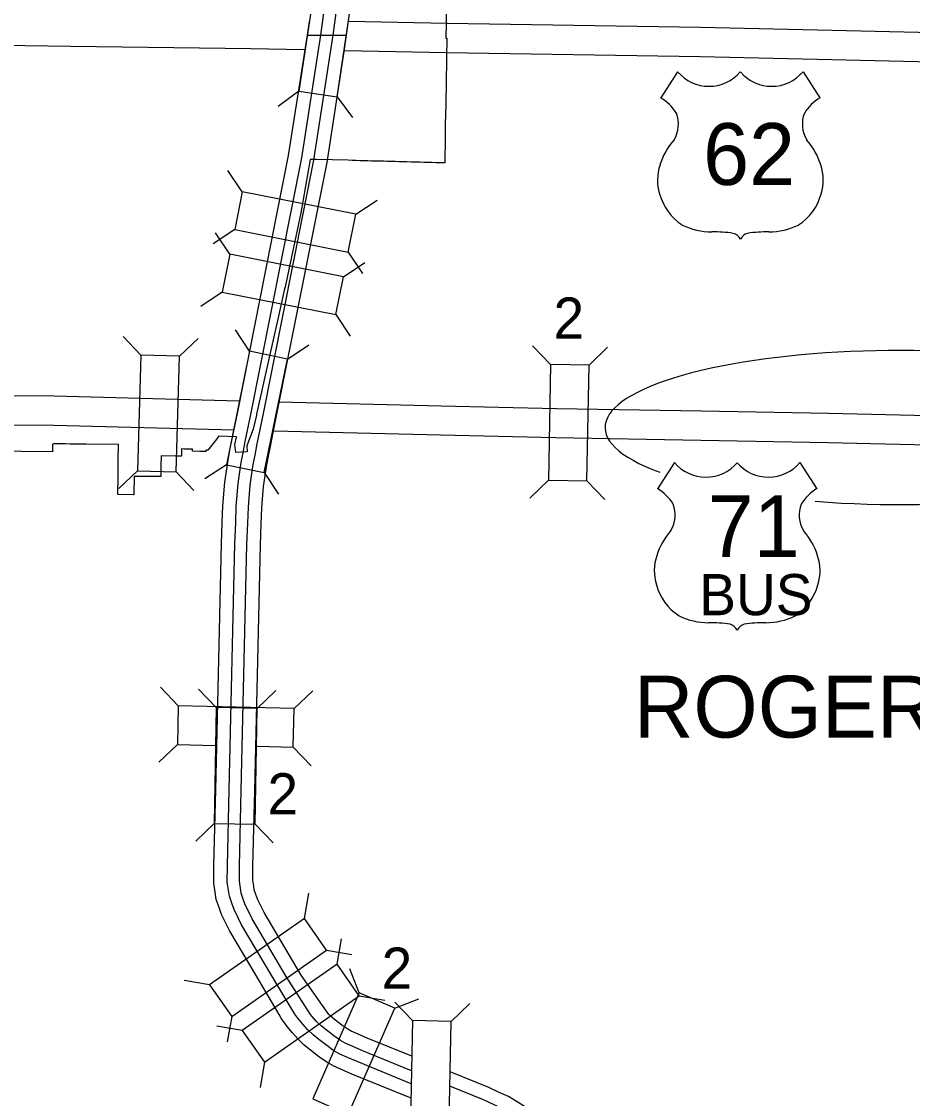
# Model space of a CAD drawing. Extents: x 309389.3 to 309420.2, y 336441.4 to 336461.2.
# Drawn here: x 309391.086 to 309392.47, y 336456.181 to 336457.854 of the extents above; entities that cross this region are included whole.
import ezdxf

# ---------------------------------------------------------------- set-up
doc = ezdxf.new("R2010")
doc.units = 0
for name, color, linetype in [('Level 24', 7, 'Continuous'), ('Level 37', 7, 'Continuous'), ('Level 62', 7, 'Continuous'), ('R_Axis Annot', 7, 'Continuous'), ('R_Detour Annot', 7, 'Continuous'), ('R_Erosion', 7, 'Continuous'), ('R_Exist Surface Annot', 7, 'Continuous')]:
    doc.layers.add(name, color=color, linetype=linetype)

msp = doc.modelspace()

# ---------------------------------------------------------------- linework, layer by layer
at = {"layer": 'Level 24'}
for points in [[(309392.7467, 336457.8326), (309392.5464, 336457.8352), (309392.3457, 336457.8401), (309392.1411, 336457.8446), (309391.7472, 336457.8507), (309391.5941, 336457.8538)], [(309391.1625, 336457.8151), (309390.8396, 336457.8198), (309390.8242, 336457.8199)], [(309391.525, 336457.8098), (309391.4422, 336457.8115), (309391.1625, 336457.8151)], [(309392.7234, 336457.7875), (309392.5456, 336457.7898), (309392.3447, 336457.7946), (309392.1403, 336457.7991), (309391.7464, 336457.8052), (309391.5876, 336457.8085)]]:
    msp.add_lwpolyline(points, dxfattribs=at)
at = {"layer": 'Level 37'}
for p, q in [((309391.5168, 336457.746), (309391.4847, 336457.7222)), ((309391.5762, 336457.7371), (309391.5999, 336457.7049)), ((309391.4288, 336457.5896), (309391.4065, 336457.6228)), ((309391.6053, 336457.5545), (309391.6386, 336457.5767)), ((309391.4171, 336457.5307), (309391.3838, 336457.5085)), ((309391.4095, 336457.4925), (309391.3872, 336457.5258)), ((309391.5936, 336457.4957), (309391.6158, 336457.4624)), ((309391.586, 336457.4574), (309391.6193, 336457.4796)), ((309391.3978, 336457.4337), (309391.3645, 336457.4114)), ((309391.5743, 336457.3986), (309391.5965, 336457.3653)), ((309391.4401, 336457.3417), (309391.4181, 336457.375)), ((309391.2711, 336457.3357), (309391.2435, 336457.3648)), ((309391.331, 336457.3341), (309391.3601, 336457.3617)), ((309391.4989, 336457.3297), (309391.5323, 336457.3517)), ((309391.9076, 336457.3213), (309391.8798, 336457.35)), ((309391.9676, 336457.3202), (309391.9963, 336457.348)), ((309391.9076, 336457.3213), (309391.9044, 336457.1413)), ((309391.9676, 336457.3202), (309391.9076, 336457.3213)), ((309391.9644, 336457.1402), (309391.9676, 336457.3202)), ((309391.2662, 336457.1558), (309391.2372, 336457.1283)), ((309391.3262, 336457.1542), (309391.3537, 336457.1252)), ((309391.4041, 336457.1653), (309391.3707, 336457.1433)), ((309391.4629, 336457.1533), (309391.485, 336457.1199)), ((309391.9044, 336457.1413), (309391.8756, 336457.1135)), ((309391.9044, 336457.1413), (309391.9644, 336457.1402)), ((309391.9644, 336457.1402), (309391.9922, 336457.1115)), ((309391.3294, 336456.7909), (309391.3018, 336456.8198)), ((309391.3884, 336456.7882), (309391.3606, 336456.8169)), ((309391.4522, 336456.787), (309391.481, 336456.8148)), ((309391.5094, 336456.7867), (309391.5383, 336456.8143)), ((309391.3294, 336456.7909), (309391.328, 336456.7309)), ((309391.5094, 336456.7867), (309391.3294, 336456.7909)), ((309391.3884, 336456.7882), (309391.3853, 336456.6082)), ((309391.4522, 336456.787), (309391.3884, 336456.7882)), ((309391.449, 336456.6071), (309391.4522, 336456.787)), ((309391.508, 336456.7267), (309391.5094, 336456.7867)), ((309391.328, 336456.7309), (309391.2991, 336456.7033)), ((309391.328, 336456.7309), (309391.3865, 336456.7295)), ((309391.4518, 336456.728), (309391.508, 336456.7267)), ((309391.5356, 336456.6978), (309391.508, 336456.7267)), ((309391.3853, 336456.6082), (309391.3565, 336456.5804)), ((309391.3853, 336456.6082), (309391.449, 336456.6071)), ((309391.449, 336456.6071), (309391.4768, 336456.5783)), ((309391.5253, 336456.4606), (309391.5323, 336456.5)), ((309391.5762, 336456.3898), (309391.5831, 336456.4291)), ((309391.5598, 336456.4114), (309391.5992, 336456.4045)), ((309391.6107, 336456.3452), (309391.5962, 336456.3824)), ((309391.378, 336456.3572), (309391.3386, 336456.3641)), ((309391.6107, 336456.3406), (309391.6501, 336456.3337)), ((309391.6657, 336456.3211), (309391.703, 336456.3357)), ((309391.6935, 336456.3018), (309391.6657, 336456.3306)), ((309391.7534, 336456.3006), (309391.7823, 336456.3283)), ((309391.4124, 336456.3081), (309391.4055, 336456.2687)), ((309391.4288, 336456.2864), (309391.3894, 336456.2933)), ((309391.4633, 336456.2373), (309391.4564, 336456.1979))]:
    msp.add_line(p, q, dxfattribs=at)
for points in [[(309391.5436, 336457.924), (309391.5168, 336457.746), (309391.5762, 336457.7371), (309391.6029, 336457.9151)], [(309391.6053, 336457.5545), (309391.4288, 336457.5896), (309391.4171, 336457.5307), (309391.5936, 336457.4957)], [(309391.586, 336457.4574), (309391.4095, 336457.4925), (309391.3978, 336457.4337), (309391.5743, 336457.3986)], [(309391.2711, 336457.3357), (309391.2662, 336457.1558), (309391.3262, 336457.1542), (309391.331, 336457.3341)], [(309391.4401, 336457.3417), (309391.4041, 336457.1653), (309391.4629, 336457.1533), (309391.4989, 336457.3297)], [(309391.4124, 336456.3081), (309391.5598, 336456.4114), (309391.5253, 336456.4606), (309391.378, 336456.3572)], [(309391.4633, 336456.2373), (309391.6107, 336456.3406), (309391.5762, 336456.3898), (309391.4288, 336456.2864)], [(309391.5935, 336456.1562), (309391.6657, 336456.3211), (309391.6107, 336456.3452), (309391.5386, 336456.1803)], [(309391.6935, 336456.3018), (309391.6899, 336456.1218), (309391.7499, 336456.1206), (309391.7534, 336456.3006)]]:
    msp.add_lwpolyline(points, close=True, dxfattribs=at)
at = {"layer": 'Level 62'}
for points in [[(309391.7468, 336457.9093), (309391.7455, 336457.8509), (309391.745, 336457.8281), (309391.7466, 336457.8281), (309391.7465, 336457.8234), (309391.7462, 336457.8029), (309391.7461, 336457.7948), (309391.7455, 336457.7586), (309391.7454, 336457.7525), (309391.7451, 336457.7343), (309391.7449, 336457.7233), (309391.7449, 336457.7228), (309391.7449, 336457.7199), (309391.7448, 336457.7154), (309391.7443, 336457.6886), (309391.7443, 336457.6881), (309391.7443, 336457.6877), (309391.7443, 336457.6872), (309391.7439, 336457.6645), (309391.7439, 336457.6639), (309391.7436, 336457.6443), (309391.7435, 336457.6438), (309391.7434, 336457.6348), (309391.7434, 336457.6342), (309391.7356, 336457.6345), (309391.7295, 336457.6346), (309391.7231, 336457.6348), (309391.717, 336457.635), (309391.7109, 336457.6351), (309391.7045, 336457.6353), (309391.6984, 336457.6355), (309391.692, 336457.6356), (309391.6844, 336457.6359), (309391.6784, 336457.636), (309391.6723, 336457.6361), (309391.6662, 336457.6363), (309391.6602, 336457.6365), (309391.6541, 336457.6367), (309391.648, 336457.6369), (309391.6431, 336457.637), (309391.642, 336457.6371), (309391.6359, 336457.6372), (309391.6298, 336457.6373), (309391.6238, 336457.6375), (309391.6177, 336457.6377), (309391.6116, 336457.6378), (309391.6056, 336457.6381), (309391.5995, 336457.6382), (309391.5935, 336457.6384), (309391.5442, 336457.6397), (309391.5425, 336457.6397), (309391.5345, 336457.6396), (309391.5198, 336457.5566), (309391.4952, 336457.4416), (309391.4945, 336457.4386), (309391.4842, 336457.3916), (309391.4718, 336457.3365), (309391.4511, 336457.2439), (309391.4507, 336457.2425), (309391.4456, 336457.2208), (309391.4357, 336457.1949), (309391.4365, 336457.1857), (309391.4186, 336457.1846), (309391.4173, 336457.1967), (309391.4198, 336457.2081), (309391.4198, 336457.2089), (309391.4188, 336457.2089), (309391.3923, 336457.2097), (309391.3895, 336457.2058), (309391.3813, 336457.1956), (309391.3753, 336457.1882), (309391.3747, 336457.1882), (309391.3724, 336457.1882), (309391.3723, 336457.1864), (309391.3723, 336457.1859), (309391.3708, 336457.1859), (309391.3686, 336457.186), (309391.3636, 336457.1862), (309391.3629, 336457.1862), (309391.3629, 336457.1862), (309391.3514, 336457.1865), (309391.3515, 336457.1894), (309391.338, 336457.1898), (309391.3346, 336457.1899)], [(309391.3346, 336457.1899), (309391.3344, 336457.1787), (309391.3326, 336457.1787), (309391.3262, 336457.1788), (309391.3026, 336457.1791), (309391.3023, 336457.1632), (309391.3021, 336457.1471), (309391.2998, 336457.1471), (309391.2978, 336457.1471), (309391.2782, 336457.1471), (309391.2762, 336457.1471), (309391.2607, 336457.1472), (309391.2605, 336457.1207), (309391.2605, 336457.1188), (309391.26, 336457.1188), (309391.2356, 336457.119), (309391.2357, 336457.1468), (309391.236, 336457.1718), (309391.2364, 336457.1968), (309391.1858, 336457.1973), (309391.1811, 336457.1974), (309391.1615, 336457.1976), (309391.1536, 336457.1977), (309391.1388, 336457.1978), (309391.1384, 336457.1978), (309391.1364, 336457.1979), (309391.1362, 336457.1979), (309391.1339, 336457.1968), (309391.1337, 336457.1857), (309391.0858, 336457.1861), (309391.0616, 336457.1863)]]:
    msp.add_lwpolyline(points, dxfattribs=at)
at = {"layer": 'R_Axis Annot'}
for points in [[(309391.5299, 336457.8328), (309391.5332, 336457.8539)], [(309391.4162, 336457.2191), (309391.1358, 336457.2266), (309390.9317, 336457.2281), (309390.8884, 336457.228), (309390.879, 336457.2288), (309390.8694, 336457.2314), (309390.8606, 336457.2353), (309390.8547, 336457.2387), (309390.8474, 336457.2426), (309390.8394, 336457.2485), (309390.8316, 336457.2573), (309390.825, 336457.2666), (309390.8136, 336457.2891)], [(309391.4241, 336457.2643), (309391.1366, 336457.2721), (309390.9318, 336457.2735)], [(309392.7145, 336457.2356), (309392.5398, 336457.2405), (309392.3399, 336457.2452), (309392.1422, 336457.2485), (309391.9172, 336457.2524), (309391.7378, 336457.2566), (309391.4857, 336457.2628)], [(309392.7175, 336457.19), (309392.5386, 336457.195), (309392.339, 336457.1997), (309392.1414, 336457.203), (309391.9163, 336457.207), (309391.7367, 336457.2112), (309391.478, 336457.2175)]]:
    msp.add_lwpolyline(points, dxfattribs=at)
at = {"layer": 'R_Detour Annot'}
for p, q in [((309392.1053, 336457.776), (309392.0791, 336457.7354)), ((309392.3003, 336457.776), (309392.3265, 336457.7354)), ((309392.1003, 336457.1688), (309392.0741, 336457.1282)), ((309392.2953, 336457.1688), (309392.3216, 336457.1282))]:
    msp.add_line(p, q, dxfattribs=at)
for centre, radius, start, end in [((309392.1541, 336457.8171), 0.0638, 220.075, 319.6701), ((309392.2514, 336457.8171), 0.0638, 220.3299, 319.925), ((309392.0448, 336457.6765), 0.0681, 30.7809, 59.9883), ((309392.3608, 336457.6765), 0.0681, 120.0117, 149.2191), ((309392.0598, 336457.6945), 0.0467, 328.8105, 21.2108), ((309392.3458, 336457.6945), 0.0467, 158.7892, 211.1895), ((309392.1819, 336457.5988), 0.109, 138.9565, 162.6913), ((309392.2236, 336457.5988), 0.109, 17.3087, 41.0435), ((309392.146, 336457.6077), 0.072, 160.9576, 197.3819), ((309392.2596, 336457.6077), 0.072, 342.6181, 19.0424), ((309392.1577, 336457.6079), 0.0833, 195.1074, 237.1312), ((309392.2479, 336457.6079), 0.0833, 302.8688, 344.8926), ((309392.1592, 336457.6341), 0.107, 244.0771, 269.5779), ((309392.2463, 336457.6341), 0.107, 270.4221, 295.9229), ((309392.1617, 336457.3312), 0.196, 81.1942, 90.9539), ((309392.1862, 336457.5069), 0.0188, 28.0342, 72.9864), ((309392.2194, 336457.5069), 0.0188, 107.0136, 151.9658), ((309392.2439, 336457.3312), 0.196, 89.0461, 98.8058), ((309392.1492, 336457.2099), 0.0638, 220.075, 319.6701), ((309392.2465, 336457.2099), 0.0638, 220.3299, 319.925), ((309392.0399, 336457.0693), 0.0681, 30.7809, 59.9883), ((309392.3558, 336457.0693), 0.0681, 120.0117, 149.2191), ((309392.0548, 336457.0873), 0.0467, 328.8105, 21.2108), ((309392.3408, 336457.0873), 0.0467, 158.7892, 211.1895), ((309392.177, 336456.9916), 0.109, 138.9565, 162.6913), ((309392.2187, 336456.9916), 0.109, 17.3087, 41.0435), ((309392.141, 336457.0005), 0.072, 160.9576, 197.3819), ((309392.2547, 336457.0005), 0.072, 342.6181, 19.0424), ((309392.1527, 336457.0007), 0.0833, 195.1074, 237.1312), ((309392.2429, 336457.0007), 0.0833, 302.8688, 344.8926), ((309392.1543, 336457.0269), 0.107, 244.0771, 269.5779), ((309392.1568, 336456.724), 0.196, 81.1942, 90.9539), ((309392.1813, 336456.8997), 0.0188, 28.0342, 72.9864), ((309392.2144, 336456.8997), 0.0188, 107.0136, 151.9658), ((309392.2389, 336456.724), 0.196, 89.0461, 98.8058), ((309392.2414, 336457.0269), 0.107, 270.4221, 295.9229)]:
    msp.add_arc(centre, radius, start, end, dxfattribs=at)
at = {"layer": 'R_Erosion'}
for points in [[(309391.551, 336457.8328), (309391.5642, 336457.9323), (309391.5692, 336457.9652), (309391.5728, 336457.9769), (309391.5743, 336457.9815), (309391.5765, 336457.9888), (309391.5796, 336457.9963), (309391.5817, 336458.0008), (309391.5836, 336458.0044), (309391.5847, 336458.0072), (309391.5891, 336458.0143), (309391.5918, 336458.0192), (309391.5955, 336458.0246), (309391.6042, 336458.0378), (309391.608, 336458.0423), (309391.7194, 336458.2076), (309391.7222, 336458.2118)], [(309391.5701, 336457.8328), (309391.5829, 336457.9296), (309391.5877, 336457.961), (309391.5908, 336457.9712), (309391.5923, 336457.9757), (309391.5944, 336457.9824), (309391.597, 336457.9888), (309391.5987, 336457.9925), (309391.6007, 336457.9962), (309391.6017, 336457.9986), (309391.6055, 336458.0048), (309391.608, 336458.0093), (309391.6113, 336458.0141), (309391.6193, 336458.0264), (309391.6231, 336458.0308), (309391.7352, 336458.1971), (309391.7392, 336458.2032)], [(309391.5907, 336457.8328), (309391.6036, 336457.9267), (309391.6081, 336457.9564), (309391.6107, 336457.9648), (309391.6122, 336457.9694), (309391.614, 336457.9753), (309391.6162, 336457.9806), (309391.6174, 336457.9832), (309391.6195, 336457.9872), (309391.6203, 336457.9891), (309391.6235, 336457.9943), (309391.6258, 336457.9984), (309391.6286, 336458.0026), (309391.636, 336458.0138), (309391.6397, 336458.0181), (309391.7525, 336458.1855), (309391.7582, 336458.1941)], [(309391.4217, 336457.2478), (309391.5008, 336457.6458), (309391.5299, 336457.8328), (309391.5907, 336457.8328)], [(309391.4421, 336457.2437), (309391.5213, 336457.6421), (309391.551, 336457.8328)], [(309391.4607, 336457.24), (309391.54, 336457.6388), (309391.5701, 336457.8328)], [(309391.5872, 336457.8072), (309391.5907, 336457.8328)], [(309391.4811, 336457.236), (309391.5605, 336457.6352), (309391.5872, 336457.8072)], [(309391.3875, 336456.6606), (309391.3963, 336457.0431), (309391.3978, 336457.0759), (309391.3985, 336457.1016), (309391.4015, 336457.1385), (309391.4067, 336457.1726), (309391.4096, 336457.1879), (309391.4131, 336457.2057), (309391.4217, 336457.2478)], [(309391.4083, 336456.6606), (309391.4172, 336457.0424), (309391.4186, 336457.0752), (309391.4193, 336457.1005), (309391.4222, 336457.1361), (309391.4272, 336457.1691), (309391.43, 336457.1839), (309391.4335, 336457.2015), (309391.4421, 336457.2437)], [(309391.4273, 336456.6595), (309391.4361, 336457.0417), (309391.4375, 336457.0745), (309391.4383, 336457.0995), (309391.441, 336457.1339), (309391.4459, 336457.1659), (309391.4486, 336457.1802), (309391.4521, 336457.1978), (309391.4607, 336457.24)], [(309391.4481, 336456.6588), (309391.4569, 336457.041), (309391.4583, 336457.0737), (309391.4591, 336457.0983), (309391.4617, 336457.1315), (309391.4664, 336457.1624), (309391.4691, 336457.1763), (309391.4725, 336457.1936), (309391.477, 336457.2155), (309391.4811, 336457.236)], [(309391.486, 336456.3114), (309391.4502, 336456.3718), (309391.4093, 336456.4408), (309391.4037, 336456.4522), (309391.3967, 336456.4665), (309391.3929, 336456.4777), (309391.3884, 336456.4902), (309391.3867, 336456.5016), (309391.3846, 336456.5154), (309391.3848, 336456.5427), (309391.3875, 336456.6606)], [(309391.5105, 336456.3121), (309391.4748, 336456.3712), (309391.4276, 336456.4507), (309391.4224, 336456.4614), (309391.416, 336456.4745), (309391.4126, 336456.4845), (309391.4087, 336456.4953), (309391.4073, 336456.5047), (309391.4055, 336456.5169), (309391.4056, 336456.5424), (309391.4083, 336456.6606)], [(309391.5347, 336456.3115), (309391.4971, 336456.3706), (309391.4443, 336456.4598), (309391.4394, 336456.4697), (309391.4335, 336456.4817), (309391.4304, 336456.4907), (309391.4272, 336456.4999), (309391.426, 336456.5075), (309391.4244, 336456.5183), (309391.4246, 336456.5422), (309391.4273, 336456.6595)], [(309391.5632, 336456.3113), (309391.5203, 336456.3724), (309391.4626, 336456.4697), (309391.4581, 336456.4789), (309391.4528, 336456.4897), (309391.4501, 336456.4976), (309391.4475, 336456.505), (309391.4467, 336456.5106), (309391.4453, 336456.5198), (309391.4454, 336456.5419), (309391.4481, 336456.6588)], [(309391.6915, 336456.2039), (309391.6073, 336456.2381), (309391.5923, 336456.2447), (309391.5804, 336456.2497), (309391.5713, 336456.2549), (309391.56, 336456.2631), (309391.5476, 336456.2725), (309391.5389, 336456.2796), (309391.5299, 336456.288), (309391.5228, 336456.2962), (309391.5152, 336456.3056), (309391.5105, 336456.3121)], [(309391.6911, 336456.1815), (309391.5992, 336456.2189), (309391.5841, 336456.2255), (309391.5712, 336456.2309), (309391.56, 336456.2373), (309391.5475, 336456.2463), (309391.5347, 336456.2562), (309391.5252, 336456.2639), (309391.5149, 336456.2735), (309391.5068, 336456.2828), (309391.4986, 336456.2929), (309391.4894, 336456.3057), (309391.486, 336456.3114)], [(309391.6919, 336456.2241), (309391.6147, 336456.2555), (309391.5997, 336456.2621), (309391.5888, 336456.2667), (309391.5816, 336456.2708), (309391.5713, 336456.2782), (309391.5593, 336456.2874), (309391.5513, 336456.2939), (309391.5435, 336456.3012), (309391.5373, 336456.3084), (309391.5347, 336456.3115)], [(309391.6924, 336456.2465), (309391.6228, 336456.2747), (309391.608, 336456.2812), (309391.598, 336456.2854), (309391.5928, 336456.2884), (309391.5837, 336456.2949), (309391.5722, 336456.3038), (309391.565, 336456.3096), (309391.5632, 336456.3113)], [(309392.1065, 336455.8123), (309391.9308, 336456.1017), (309391.9236, 336456.1127), (309391.9173, 336456.1202), (309391.912, 336456.1269), (309391.9041, 336456.1362), (309391.8954, 336456.1447), (309391.887, 336456.1529), (309391.8763, 336456.1612), (309391.8674, 336456.1685), (309391.856, 336456.1755), (309391.8423, 336456.1839), (309391.8279, 336456.1903), (309391.812, 336456.1978), (309391.7519, 336456.2222)], [(309392.0892, 336455.8008), (309391.9132, 336456.0906), (309391.9068, 336456.1002), (309391.9011, 336456.107), (309391.8959, 336456.1137), (309391.8888, 336456.122), (309391.8809, 336456.1298), (309391.8733, 336456.1372), (309391.8633, 336456.1449), (309391.8553, 336456.1515), (309391.8451, 336456.1578), (309391.8326, 336456.1654), (309391.8192, 336456.1713), (309391.8036, 336456.1787), (309391.7515, 336456.1999)]]:
    msp.add_lwpolyline(points, dxfattribs=at)
at = {"layer": 'R_Exist Surface Annot'}
msp.add_ellipse((309392.4506, 336457.2233), major_axis=(0.4581, 0), ratio=0.261367, start_param=4.420709, end_param=10.044947, dxfattribs=at)

# ---------------------------------------------------------------- texts
at = {"layer": 'Level 37'}
for p in [(309391.9124, 336457.3612), (309391.4679, 336456.6222), (309391.6453, 336456.3514)]:
    msp.add_text('2', height=0.064, dxfattribs=at).set_placement(p)
at = {"layer": 'Level 62'}
msp.add_text('ROGERS', height=0.096, dxfattribs=at).set_placement((309392.0371, 336456.7416))
at = {"layer": 'R_Detour Annot'}
for s, height, p in [('62', 0.096, (309392.1449, 336457.6001)), ('71', 0.096, (309392.152, 336457.022)), ('BUS', 0.064, (309392.1389, 336456.9316))]:
    msp.add_text(s, height=height, dxfattribs=at).set_placement(p)

doc.saveas('drawing.dxf')
